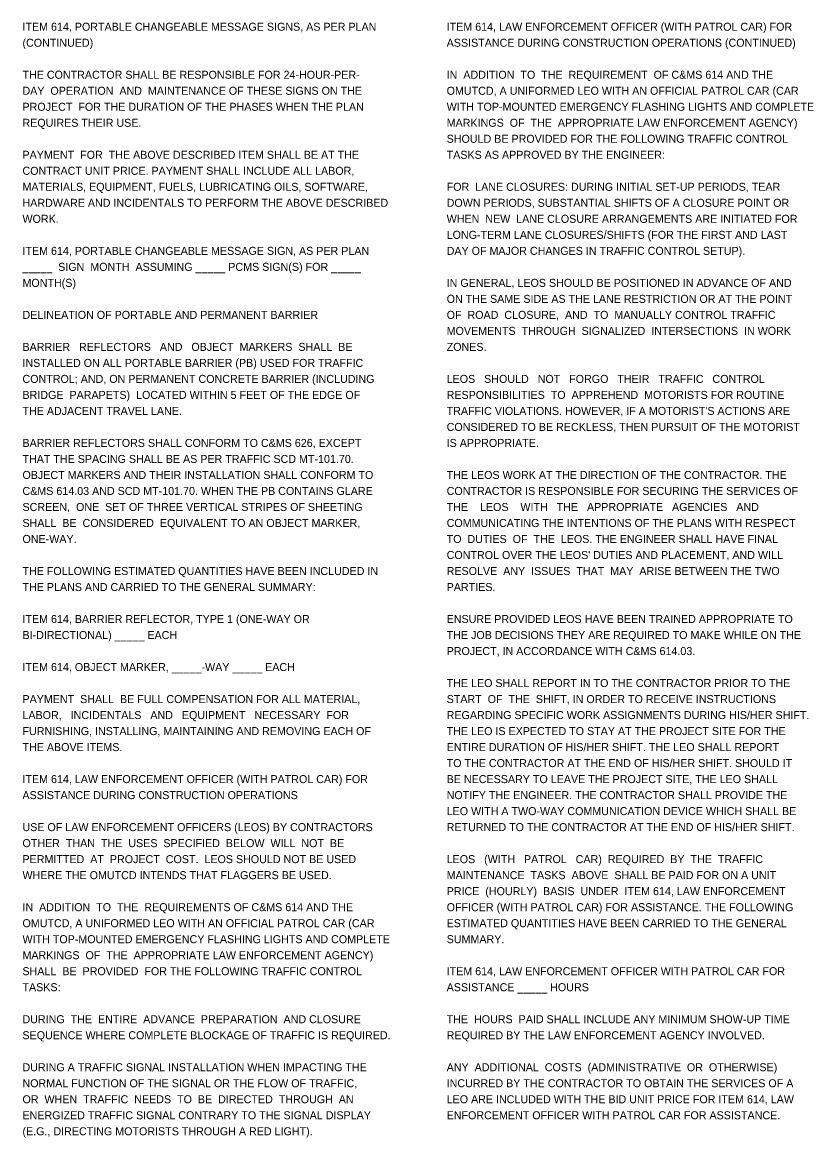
# Model space of a CAD drawing. Extents: x -31.1 to 65.6, y 0 to 22.
# Drawn here: x 51.74 to 65.58, y 1.64 to 21.15 of the extents above; entities that cross this region are included whole.
import ezdxf

# ---------------------------------------------------------------- set-up
doc = ezdxf.new("R2010")
doc.units = 0
doc.layers.add('SH_Text', color=7, linetype='Continuous')
doc.layers.add('TX_P_1', color=7, linetype='Continuous')

msp = doc.modelspace()

# ---------------------------------------------------------------- texts
at = {"layer": 'SH_Text'}
for s, p in [('ITEM 614, LAW ENFORCEMENT OFFICER (WITH PATROL CAR) FOR', (59.16, 21)), ('ASSISTANCE DURING CONSTRUCTION OPERATIONS (CONTINUED)', (59.16, 20.72)), ('THE CONTRACTOR SHALL BE RESPONSIBLE FOR 24-HOUR-PER-', (51.74, 20.16)), ('IN  ADDITION  TO  THE  REQUIREMENT  OF C&MS 614 AND THE', (59.16, 20.16)), ('DAY  OPERATION  AND  MAINTENANCE OF THESE SIGNS ON THE', (51.74, 19.88)), ('OMUTCD, A UNIFORMED LEO WITH AN OFFICIAL PATROL CAR (CAR', (59.16, 19.88)), ('PROJECT  FOR THE DURATION OF THE PHASES WHEN THE PLAN', (51.74, 19.6)), ('WITH TOP-MOUNTED EMERGENCY FLASHING LIGHTS AND COMPLETE', (59.16, 19.6)), ('REQUIRES THEIR USE.', (51.74, 19.32)), ('MARKINGS  OF  THE  APPROPRIATE LAW ENFORCEMENT AGENCY)', (59.16, 19.32)), ('SHOULD BE PROVIDED FOR THE FOLLOWING TRAFFIC CONTROL', (59.16, 19.04)), ('PAYMENT  FOR  THE ABOVE DESCRIBED ITEM SHALL BE AT THE', (51.74, 18.76)), ('TASKS AS APPROVED BY THE ENGINEER:', (59.16, 18.76)), ('CONTRACT UNIT PRICE. PAYMENT SHALL INCLUDE ALL LABOR,', (51.74, 18.48)), ('MATERIALS, EQUIPMENT, FUELS, LUBRICATING OILS, SOFTWARE,', (51.74, 18.2)), ('FOR  LANE CLOSURES: DURING INITIAL SET-UP PERIODS, TEAR', (59.16, 18.2)), ('HARDWARE AND INCIDENTALS TO PERFORM THE ABOVE DESCRIBED', (51.74, 17.92)), ('DOWN PERIODS, SUBSTANTIAL SHIFTS OF A CLOSURE POINT OR', (59.16, 17.92)), ('WORK.', (51.74, 17.64)), ('WHEN  NEW  LANE CLOSURE ARRANGEMENTS ARE INITIATED FOR', (59.16, 17.64)), ('LONG-TERM LANE CLOSURES/SHIFTS (FOR THE FIRST AND LAST', (59.16, 17.36)), ('ITEM 614, PORTABLE CHANGEABLE MESSAGE SIGN, AS PER PLAN', (51.74, 17.08)), ('DAY OF MAJOR CHANGES IN TRAFFIC CONTROL SETUP).', (59.16, 17.08)), ('_____  SIGN  MONTH  ASSUMING _____ PCMS SIGN(S) FOR _____', (51.74, 16.8)), ('MONTH(S)', (51.74, 16.52)), ('IN GENERAL, LEOS SHOULD BE POSITIONED IN ADVANCE OF AND', (59.16, 16.52)), ('ON THE SAME SIDE AS THE LANE RESTRICTION OR AT THE POINT', (59.16, 16.24)), ('DELINEATION OF PORTABLE AND PERMANENT BARRIER', (51.74, 15.96)), ('OF  ROAD  CLOSURE,  AND  TO  MANUALLY CONTROL TRAFFIC', (59.16, 15.96)), ('MOVEMENTS  THROUGH  SIGNALIZED  INTERSECTIONS  IN WORK', (59.16, 15.68)), ('BARRIER   REFLECTORS   AND   OBJECT  MARKERS  SHALL  BE', (51.74, 15.4)), ('ZONES.', (59.16, 15.4)), ('INSTALLED ON ALL PORTABLE BARRIER (PB) USED FOR TRAFFIC', (51.74, 15.12)), ('CONTROL; AND, ON PERMANENT CONCRETE BARRIER (INCLUDING', (51.74, 14.84)), ('LEOS   SHOULD   NOT   FORGO   THEIR   TRAFFIC   CONTROL', (59.16, 14.84)), ('BRIDGE  PARAPETS)  LOCATED WITHIN 5 FEET OF THE EDGE OF', (51.74, 14.56)), ('RESPONSIBILITIES  TO  APPREHEND  MOTORISTS FOR ROUTINE', (59.16, 14.56)), ('THE ADJACENT TRAVEL LANE.', (51.74, 14.28)), ("TRAFFIC VIOLATIONS. HOWEVER, IF A MOTORIST'S ACTIONS ARE", (59.16, 14.28)), ('CONSIDERED TO BE RECKLESS, THEN PURSUIT OF THE MOTORIST', (59.16, 14)), ('BARRIER REFLECTORS SHALL CONFORM TO C&MS 626, EXCEPT', (51.74, 13.72)), ('IS APPROPRIATE.', (59.16, 13.72)), ('THAT THE SPACING SHALL BE AS PER TRAFFIC SCD MT-101.70.', (51.74, 13.44)), ('OBJECT MARKERS AND THEIR INSTALLATION SHALL CONFORM TO', (51.74, 13.16)), ('THE LEOS WORK AT THE DIRECTION OF THE CONTRACTOR. THE', (59.16, 13.16)), ('C&MS 614.03 AND SCD MT-101.70. WHEN THE PB CONTAINS GLARE', (51.74, 12.88)), ('CONTRACTOR IS RESPONSIBLE FOR SECURING THE SERVICES OF', (59.16, 12.88)), ('SCREEN,  ONE  SET OF THREE VERTICAL STRIPES OF SHEETING', (51.74, 12.6)), ('THE    LEOS    WITH   THE   APPROPRIATE   AGENCIES   AND', (59.16, 12.6)), ('SHALL  BE  CONSIDERED  EQUIVALENT TO AN OBJECT MARKER,', (51.74, 12.32)), ('COMMUNICATING THE INTENTIONS OF THE PLANS WITH RESPECT', (59.16, 12.32)), ('ONE-WAY.', (51.74, 12.04)), ('TO  DUTIES  OF  THE  LEOS. THE ENGINEER SHALL HAVE FINAL', (59.16, 12.04)), ("CONTROL OVER THE LEOS' DUTIES AND PLACEMENT, AND WILL", (59.16, 11.76)), ('THE FOLLOWING ESTIMATED QUANTITIES HAVE BEEN INCLUDED IN', (51.74, 11.48)), ('RESOLVE  ANY  ISSUES  THAT  MAY  ARISE BETWEEN THE TWO', (59.16, 11.48)), ('THE PLANS AND CARRIED TO THE GENERAL SUMMARY:', (51.74, 11.2)), ('PARTIES.', (59.16, 11.2)), ('ITEM 614, BARRIER REFLECTOR, TYPE 1 (ONE-WAY OR', (51.74, 10.64)), ('ENSURE PROVIDED LEOS HAVE BEEN TRAINED APPROPRIATE TO', (59.16, 10.64)), ('BI-DIRECTIONAL) _____ EACH', (51.74, 10.36)), ('THE JOB DECISIONS THEY ARE REQUIRED TO MAKE WHILE ON THE', (59.16, 10.36)), ('PROJECT, IN ACCORDANCE WITH C&MS 614.03.', (59.16, 10.08)), ('ITEM 614, OBJECT MARKER, _____-WAY _____ EACH', (51.74, 9.8)), ('THE LEO SHALL REPORT IN TO THE CONTRACTOR PRIOR TO THE', (59.16, 9.52)), ('PAYMENT  SHALL  BE FULL COMPENSATION FOR ALL MATERIAL,', (51.74, 9.24)), ('START  OF  THE  SHIFT, IN ORDER TO RECEIVE INSTRUCTIONS', (59.16, 9.24)), ('LABOR,   INCIDENTALS   AND   EQUIPMENT   NECESSARY  FOR', (51.74, 8.96)), ('REGARDING SPECIFIC WORK ASSIGNMENTS DURING HIS/HER SHIFT.', (59.16, 8.96)), ('FURNISHING, INSTALLING, MAINTAINING AND REMOVING EACH OF', (51.74, 8.68)), ('THE LEO IS EXPECTED TO STAY AT THE PROJECT SITE FOR THE', (59.16, 8.68)), ('THE ABOVE ITEMS.', (51.74, 8.4)), ('ENTIRE DURATION OF HIS/HER SHIFT. THE LEO SHALL REPORT', (59.16, 8.4)), ('TO THE CONTRACTOR AT THE END OF HIS/HER SHIFT. SHOULD IT', (59.16, 8.12)), ('ITEM 614, LAW ENFORCEMENT OFFICER (WITH PATROL CAR) FOR', (51.74, 7.84)), ('BE NECESSARY TO LEAVE THE PROJECT SITE, THE LEO SHALL', (59.16, 7.84)), ('ASSISTANCE DURING CONSTRUCTION OPERATIONS', (51.74, 7.56)), ('NOTIFY THE ENGINEER. THE CONTRACTOR SHALL PROVIDE THE', (59.16, 7.56)), ('LEO WITH A TWO-WAY COMMUNICATION DEVICE WHICH SHALL BE', (59.16, 7.28)), ('USE OF LAW ENFORCEMENT OFFICERS (LEOS) BY CONTRACTORS', (51.74, 7)), ('RETURNED TO THE CONTRACTOR AT THE END OF HIS/HER SHIFT.', (59.16, 7)), ('OTHER  THAN  THE  USES  SPECIFIED  BELOW  WILL  NOT  BE', (51.74, 6.72)), ('PERMITTED  AT  PROJECT  COST.  LEOS SHOULD NOT BE USED', (51.74, 6.44)), ('LEOS   (WITH   PATROL   CAR)  REQUIRED  BY  THE  TRAFFIC', (59.16, 6.44)), ('WHERE THE OMUTCD INTENDS THAT FLAGGERS BE USED.', (51.74, 6.16)), ('MAINTENANCE  TASKS  ABOVE  SHALL BE PAID FOR ON A UNIT', (59.16, 6.16)), ('PRICE  (HOURLY)  BASIS  UNDER  ITEM 614, LAW ENFORCEMENT', (59.16, 5.88)), ('IN  ADDITION  TO  THE  REQUIREMENTS OF C&MS 614 AND THE', (51.74, 5.6)), ('OFFICER (WITH PATROL CAR) FOR ASSISTANCE. THE FOLLOWING', (59.16, 5.6)), ('OMUTCD, A UNIFORMED LEO WITH AN OFFICIAL PATROL CAR (CAR', (51.74, 5.32)), ('ESTIMATED QUANTITIES HAVE BEEN CARRIED TO THE GENERAL', (59.16, 5.32)), ('WITH TOP-MOUNTED EMERGENCY FLASHING LIGHTS AND COMPLETE', (51.74, 5.04)), ('SUMMARY.', (59.16, 5.04)), ('MARKINGS  OF  THE  APPROPRIATE LAW ENFORCEMENT AGENCY)', (51.74, 4.76)), ('SHALL  BE  PROVIDED  FOR THE FOLLOWING TRAFFIC CONTROL', (51.74, 4.48)), ('ITEM 614, LAW ENFORCEMENT OFFICER WITH PATROL CAR FOR', (59.16, 4.48)), ('TASKS:', (51.74, 4.2)), ('ASSISTANCE _____ HOURS', (59.16, 4.2)), ('DURING  THE  ENTIRE  ADVANCE  PREPARATION  AND CLOSURE', (51.74, 3.64)), ('THE  HOURS  PAID SHALL INCLUDE ANY MINIMUM SHOW-UP TIME', (59.16, 3.64)), ('SEQUENCE WHERE COMPLETE BLOCKAGE OF TRAFFIC IS REQUIRED.', (51.74, 3.36)), ('REQUIRED BY THE LAW ENFORCEMENT AGENCY INVOLVED.', (59.16, 3.36)), ('DURING A TRAFFIC SIGNAL INSTALLATION WHEN IMPACTING THE', (51.74, 2.8)), ('ANY  ADDITIONAL  COSTS  (ADMINISTRATIVE  OR  OTHERWISE)', (59.16, 2.8)), ('NORMAL FUNCTION OF THE SIGNAL OR THE FLOW OF TRAFFIC,', (51.74, 2.52)), ('INCURRED BY THE CONTRACTOR TO OBTAIN THE SERVICES OF A', (59.16, 2.52)), ('OR  WHEN  TRAFFIC  NEEDS  TO  BE  DIRECTED  THROUGH  AN', (51.74, 2.24)), ('LEO ARE INCLUDED WITH THE BID UNIT PRICE FOR ITEM 614, LAW', (59.16, 2.24)), ('ENERGIZED TRAFFIC SIGNAL CONTRARY TO THE SIGNAL DISPLAY', (51.74, 1.96)), ('ENFORCEMENT OFFICER WITH PATROL CAR FOR ASSISTANCE.', (59.16, 1.96)), ('(E.G., DIRECTING MOTORISTS THROUGH A RED LIGHT).', (51.74, 1.68))]:
    msp.add_text(s, height=0.14, dxfattribs=at).set_placement(p)
at = {"layer": 'TX_P_1'}
for s, p in [('ITEM 614, PORTABLE CHANGEABLE MESSAGE SIGNS, AS PER PLAN', (51.74, 21)), ('(CONTINUED)', (51.74, 20.72))]:
    msp.add_text(s, height=0.14, dxfattribs=at).set_placement(p)

doc.saveas('drawing.dxf')
